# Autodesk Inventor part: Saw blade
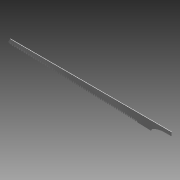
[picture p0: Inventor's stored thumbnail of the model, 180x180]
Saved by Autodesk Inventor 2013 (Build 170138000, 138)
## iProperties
Created: 2008-06
Part Number: Saw blade
Document SubType Name: Modeling
Designer: tangg
Density: 7.85 g/cm^3
Mass: 1.14139 g
Surface Area: 40.1035 cm^2
Volume: 1.14139 cm^3
Material: Alloy Steel
Author: tangg
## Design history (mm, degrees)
sketch "Sketch1"
  geometry: L1 (0, 6.35)-(-203.2, 6.35); L2 (-203.2, 6.35)-(-205.95, 1.588); L3 (-203.2, 0)-(-11.113, -5.983); L4 (-205.95, 1.588)-(-203.2, 0); L5 (0, 6.35)-(16.768, 6.35); L6 (16.768, 1.439)-(16.768, 6.35); L7 (16.768, 1.439)-(7.938, 1.328); L8 (-9.525, -3.175)-(-11.113, -5.983); A1 r 34.284 centre (7.465, -32.953) between (7.938, 1.328) and (-9.525, -3.175); 1 further point
  constraints: 16 end point, 2 point on circle, 1 centre point
  dimensions: "d2" = 120 deg angle of L1 L2; "d3" = 203.2 distance of L1.start L1.end; "d6" = 6.35 distance from line of L1 L3.start
extrude "Extrusion3" new body sketch "Sketch1" stored distance "d15" = 0.635; taper "d16" = 0 deg
sketch "Sketch2"
  geometry: L1 (-31.869, -5.337)-(-31.816, -2.797); L2 (-31.816, -2.797)-(-29.304, -5.416); L3 (-11.113, -5.983)-(-203.2, 0) reference; 1 further point
  constraints: 4 end point, 2 point on line
  dimensions: "d7" = 31.75 distance from line of point (0, 0) L1; "d8" = 2.54 vertical distance of L1.start L1.end; "d9" = 45 deg angle of L2 L1
extrude "Extrusion4" cut sketch "Sketch2" stored distance "d17" = 3.175; taper "d18" = 0 deg
body "Solid1"
pattern_linear "Rectangular Pattern1" dims "d14" = 3.175
